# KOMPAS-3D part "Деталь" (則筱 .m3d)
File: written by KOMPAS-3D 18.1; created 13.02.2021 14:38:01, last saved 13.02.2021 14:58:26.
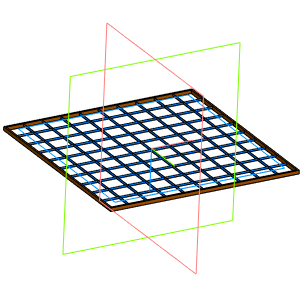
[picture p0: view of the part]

Document properties: Полное имя файла: C:\GoogleDrive\НИР\ИКИ\Компас\Сетка.m3d

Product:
- Part/product: Деталь
    Масса: 0.00232462

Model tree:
1. Эскиз:1
2. Элемент выдавливания:1
     Расстояние 1 = 1
3. Эскиз:2  (with: Элемент выдавливания:1)
4. Массив по сетке:1  (with: Эскиз:2, Элемент выдавливания:1)  (labels: v28_2_1_v27; v28_3_1_v27; v28_4_1_v27; v28_5_1_v27)  (9 pattern instances)
     Шаг 1 = 5.5; Угол раствора = 90
5. Элемент выдавливания:2
     Расстояние 1 = 55
6. Элемент выдавливания:3
     Расстояние 1 = 55
7. Элемент выдавливания:4
     Расстояние 1 = 55
8. Элемент выдавливания:5
     Расстояние 1 = 55
9. Элемент выдавливания:6
     Расстояние 1 = 55
10. Элемент выдавливания:7
     Расстояние 1 = 55
11. Элемент выдавливания:8
     Расстояние 1 = 55
12. Элемент выдавливания:9
     Расстояние 1 = 55
13. Элемент выдавливания:10
     Расстояние 1 = 55
14. Эскиз:3  (with: Элемент выдавливания:1)
15. Массив по сетке:2  (with: Эскиз:3, Элемент выдавливания:1)  (labels: v165_2_1_v164; v165_3_1_v164; v165_4_1_v164; v165_5_1_v164)  (9 pattern instances)
     Шаг 1 = 5.5; Угол раствора = 90
16. Элемент выдавливания:11  (with: Элемент выдавливания:1)
     Расстояние 1 = 54.5
17. Элемент выдавливания:12  (with: Элемент выдавливания:1)
     Расстояние 1 = 54.5
18. Элемент выдавливания:13  (with: Элемент выдавливания:1)
     Расстояние 1 = 54.5
19. Элемент выдавливания:14  (with: Элемент выдавливания:1)
     Расстояние 1 = 54.5
20. Элемент выдавливания:15  (with: Элемент выдавливания:1)
     Расстояние 1 = 54.5
21. Элемент выдавливания:16  (with: Элемент выдавливания:1)
     Расстояние 1 = 54.5
22. Элемент выдавливания:17  (with: Элемент выдавливания:1)
     Расстояние 1 = 54.5
23. Элемент выдавливания:18  (with: Элемент выдавливания:1)
     Расстояние 1 = 54.5
24. Элемент выдавливания:19  (with: Элемент выдавливания:1)
     Расстояние 1 = 54.5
